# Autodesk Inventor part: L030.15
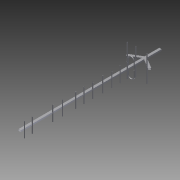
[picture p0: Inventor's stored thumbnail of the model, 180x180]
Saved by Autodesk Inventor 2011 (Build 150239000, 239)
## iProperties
Created: 2014-06
Part Number: L030.15
Document SubType Name: Modeling
Designer: Evgeny
Density: 1 g/cm^3
Author: Evgeny
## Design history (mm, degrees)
sketch "Эскиз2"
  geometry: C1 r 4 at (0, 0); C2 r 3 at (0, 0); 1 further point
  constraints: 2 centre point, 2 coincident
  dimensions: "d0" = 8 diameter of C1; "d1" = 6 diameter of C2
sketch "Эскиз3"
  geometry: L1 (0, 58)-(0, -58); L2 (50, -58)-(50, -7.5); L3 (50, 58)-(50, 7.5); A1 r 25 centre (25, 58) between (50, 58) and (0, 58); A2 r 25 centre (25, -58) between (0, -58) and (50, -58); 1 further point
  constraints: 6 end point, 4 point on circle, 3 tangent, 2 centre point, 1 collinear, 1 parallel
  dimensions: "d2" = 50 diameter of A1; "d3" = 58 vertical distance of A1.centre point (0, 0); "d4" = 25 horizontal distance of A1.centre point (0, 0); "d5" = 50 diameter of A2; "d6" = 58 vertical distance of A2.centre point (0, 0); "d7" = 15 distance of L2.end L3.end; "d8" = 7.5 vertical distance of point (0, 0) L2.end
feature "Сдвиг1" sketch "Эскиз2", "Эскиз3" dims "d9" = 0
sketch "Эскиз4"
  geometry: L1 (4, 6.5)-(24, 6.5); L2 (24, 6.5)-(24, -6.5); L3 (24, -6.5)-(4, -6.5); L4 (4, -6.5)-(4, 6.5); L5 (5, 5.5)-(23, 5.5); L6 (23, 5.5)-(23, -5.5); L7 (23, -5.5)-(5, -5.5); L8 (5, -5.5)-(5, 5.5); 1 further point
  constraints: 16 end point, 4 parallel, 2 horizontal, 2 perpendicular
  dimensions: "d10" = 4 distance from line of L4 point (0, 0); "d11" = 20 distance between parallel lines of L2 L4; "d12" = 13 distance between parallel lines of L3 L1; "d13" = 6.5 distance from line of L3 point (0, 0); "d14" = 1 distance between parallel lines of L8 L4; "d15" = 5.5 distance from line of point (0, 0) L5; "d16" = 11 distance between parallel lines of L7 L5; "d17" = 18 distance between parallel lines of L6 L8
extrude "Выдавливание1" join sketch "Эскиз4" distance "d18" = 940; taper "d20" = 0 deg; dims "d19" = 260, "d21" = 0
sketch "Эскиз5"
  geometry: C1 r 4 at (-28, 37); C2 r 3 at (-28, 37); C3 r 4 at (-28, 97); C4 r 3 at (-28, 97); C5 r 4 at (-28, 168); C6 r 3 at (-28, 168); C7 r 3 at (-28, 245); C8 r 4 at (-28, 245); C9 r 3 at (-28, 330); C10 r 4 at (-28, 330); C11 r 3 at (-28, 404.5); C12 r 4 at (-28, 404.5); C13 r 3 at (-28, 476); C14 r 4 at (-28, 476); C15 r 4 at (-28, 588); C16 r 3 at (-28, 588); C17 r 4 at (-28, 671); C18 r 3 at (-28, 671); C19 r 4 at (-28, 844); C20 r 3 at (-28, 844); C21 r 4 at (-28, 911.5); C22 r 3 at (-28, 911.5); 1 further point
  constraints: 22 centre point, 11 coincident
  dimensions: "d22" = 8 diameter of C1; "d23" = 6 diameter of C2; "d24" = 28 horizontal distance of C1.centre point (0, 0); "d25" = 37 vertical distance of C1.centre point (0, 0); "d26" = 8 diameter of C3; "d27" = 6 diameter of C4; "d28" = 60 distance of C3.centre C1.centre; "d29" = 8 diameter of C5; "d30" = 6 diameter of C6; "d31" = 71 distance of C5.centre C3.centre; "d32" = 8 diameter of C8; "d33" = 6 diameter of C7; "d34" = 77 distance of C7.centre C5.centre; "d35" = 8 diameter of C10; "d36" = 6 diameter of C9; "d37" = 85 distance of C9.centre C7.centre; "d38" = 8 diameter of C12; "d39" = 6 diameter of C11; "d40" = 74.5 distance of C11.centre C9.centre; "d41" = 8 diameter of C14; "d42" = 6 diameter of C13; "d43" = 71.5 distance of C13.centre C11.centre; "d44" = 8 diameter of C15; "d45" = 6 diameter of C16; "d46" = 112 distance of C15.centre C13.centre; "d47" = 8 diameter of C17; "d48" = 6 diameter of C18; "d49" = 83 distance of C17.centre C15.centre; "d50" = 8 diameter of C19; "d51" = 6 diameter of C20; "d52" = 173 distance of C19.centre C17.centre; "d53" = 8 diameter of C21; "d54" = 6 diameter of C22; "d55" = 67.5 distance of C21.centre C19.centre
extrude "Выдавливание2" join sketch "Эскиз5" stored distance "d56" = 123.5; taper "d57" = 0 deg
sketch "Эскиз6"
  geometry: C1 r 3 at (0, -62); C2 r 4 at (0, -62); C3 r 4 at (69, -62); C4 r 3 at (69, -62); C5 r 4 at (-97, -62); C6 r 3 at (-97, -62); 1 further point
  constraints: 6 centre point, 3 coincident
  dimensions: "d58" = 8 diameter of C2; "d59" = 6 diameter of C1; "d60" = 62 distance of C1.centre point (0, 0); "d61" = 8 diameter of C3; "d62" = 6 diameter of C4; "d63" = 69 distance of C1.centre C3.centre; "d64" = 8 diameter of C5; "d65" = 6 diameter of C6; "d66" = 97 distance of C5.centre C2.centre
extrude "Выдавливание3" join sketch "Эскиз6" stored distance "d67" = 223; taper "d68" = 0 deg
sketch "Эскиз9"
  geometry: L1 (80, -60)-(-5.647, -112); L2 (-5.647, -112)-(-5.647, -113.17); L3 (-5.647, -113.17)-(80.519, -60.855); L4 (80.519, -60.855)-(80, -60); L5 (90.38, -77.096)-(-5.647, -135.398); L6 (-5.647, -135.398)-(-5.647, -134.228); L7 (-5.647, -134.228)-(89.861, -76.241); L8 (89.861, -76.241)-(90.38, -77.096); L9 (-22.038, -112)-(-108, -60); L10 (-108, -60)-(-108.518, -60.856); L11 (-108.518, -60.856)-(-22.038, -113.169); L12 (-22.038, -113.169)-(-22.038, -112); L13 (-22, -135.398)-(-118.352, -77.113); L14 (-118.352, -77.113)-(-117.834, -76.257); L15 (-117.834, -76.257)-(-21.962, -134.252); L16 (-21.962, -134.252)-(-22, -135.398); 1 further point
  constraints: 32 end point, 6 parallel, 5 perpendicular, 4 collinear, 1 vertical
  dimensions: "d90" = 1 distance between parallel lines of L3 L1; "d91" = 60 vertical distance of L1.start point (0, 0); "d92" = 80 horizontal distance of L1.start point (0, 0); "d93" = 1 distance between parallel lines of L5 L7; "d94" = 20 distance between parallel lines of L5 L1; "d95" = 1 distance between parallel lines of L11 L9; "d96" = 60 vertical distance of L9.end point (0, 0); "d97" = 108 horizontal distance of L9.end point (0, 0); "d98" = 1 distance between parallel lines of L13 L15; "d99" = 20 distance between parallel lines of L13 L9; "d100" = 112 vertical distance of L1.end point (0, 0); "d101" = 112 vertical distance of L9.start point (0, 0)
extrude "Выдавливание6" join sketch "Эскиз9" stored distance "d102" = 13; taper "d103" = 0 deg
sketch "Эскиз10"
  geometry: L1 (-94.38, 1017.096)-(0, 1074.398) reference; L2 (0, 1073.228)-(0, 1052.17) reference; L3 (0, 1051)-(-75.006, 1005.46) reference; L4 (94.739, 1005.602)-(20, 1050.813) reference; L5 (20, 1051.982)-(20, 1073.019) reference; L6 (-84, 1000)-(-94.38, 1017.096); L7 (0, 1074.398)-(-94.38, 1017.096); L8 (0, 1074.398)-(0, 1051); L9 (-84, 1000)-(0, 1051); L10 (20, 1050.813)-(104, 1000); L11 (114.352, 1017.113)-(104, 1000); L12 (114.352, 1017.113)-(20, 1074.188); L13 (20, 1074.188)-(20, 1050.813); 1 further point
  constraints: 16 end point, 4 collinear, 4 perpendicular
extrude "Выдавливание7" join sketch "Эскиз10" distance "d104" = 1; taper "d105" = 0 deg
sketch "Эскиз11"
  geometry: L1 (20, -111.982)-(20, -133.019) reference; L2 (104.518, -60.856)-(20, -111.982) reference; L3 (104, -60)-(104.518, -60.856) reference; L4 (20, 37)-(20, -110.813) reference; L5 (20, 97)-(20, 37) reference; L6 (20, 168)-(20, 97) reference; L7 (20, 245)-(20, 168) reference; L8 (20, 330)-(20, 245) reference; L9 (20, 404.5)-(20, 330) reference; L10 (20, 476)-(20, 404.5) reference; L11 (20, 588)-(20, 476) reference; L12 (20, 671)-(20, 588) reference; L13 (20, 844)-(20, 671) reference; L14 (20, 911.5)-(20, 844) reference; L15 (20, 940)-(20, 911.5) reference; L16 (20, 940)-(0, 940) reference; L17 (0, 940)-(0, 0) reference; L18 (0, 0)-(0, -62) reference; L19 (0, -62)-(0, -111) reference; L20 (-75.006, -65.46)-(0, -111) reference; L21 (-84, -60)-(-75.145, -65.377) reference; L22 (-84.519, -60.855)-(-84, -60) reference; L23 (0, -112.17)-(-84.519, -60.855) reference; L24 (0, -112.17)-(0, -133.228) reference; L25 (-93.861, -76.241)-(0, -133.228) reference; L26 (-94.38, -77.096)-(-93.861, -76.241) reference; L27 (0, -134.398)-(-94.38, -77.096) reference; L28 (0, -134.398)-(0, -260) reference; L29 (0, -260)-(20, -260) reference; L30 (20, -134.188)-(20, -260) reference; L31 (114.352, -77.113)-(20, -134.188) reference; L32 (113.834, -76.257)-(114.352, -77.113) reference; L33 (20, -133.019)-(113.834, -76.257) reference; L34 (104, -60)-(114.352, -77.113); L35 (114.352, -77.113)-(20, -134.188); L36 (20, -134.398)-(20, -110.813); L37 (20, -110.813)-(104, -60); L38 (0, -111)-(0, -134.398); L39 (0, -134.398)-(-94.38, -77.096); L40 (-94.38, -77.096)-(-84, -60); L41 (-84, -60)-(0, -111); A1 r 4 centre (-73, -62) between (-75.145, -65.377) and (-75.006, -65.46) reference; 1 further point
  constraints: 16 end point, 4 collinear, 3 perpendicular, 2 point on line
extrude "Выдавливание8" join sketch "Эскиз11" distance "d106" = 1; taper "d107" = 0 deg
node "Твердое тело1"
